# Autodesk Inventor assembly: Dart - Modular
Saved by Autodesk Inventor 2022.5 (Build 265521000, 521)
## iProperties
Created: 2025-01
Part Number: Dart - Modular
Document SubType Name: Assembly
Designer: AdminForWorker
Title: Dart - Modular v12
Author: AdminForWorker
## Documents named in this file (4)
- c:\worker\convert-fusion-r06-cosv3\tmp\job-1\21\temp\files\90c813e5-3d50-4192-b371-2f6eccf932a4\4eac9b11-f6fd-4ff3-90d4-f019b96032f5.iam
- c:\worker\convert-fusion-r06-cosv3\tmp\job-1\21\temp\files\90c813e5-3d50-4192-b371-2f6eccf932a4\Modular - Placebo - Bayonet Connector v4.ipt
- c:\worker\convert-fusion-r06-cosv3\tmp\job-1\21\temp\files\90c813e5-3d50-4192-b371-2f6eccf932a4\Dart Modular.ipt
- c:\worker\convert-fusion-r06-cosv3\tmp\job-1\21\temp\files\90c813e5-3d50-4192-b371-2f6eccf932a4\Modular - Placedo - Cord Set v4.ipt
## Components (3 placed, 3 different names)
1. Modular - Placebo - Bayonet Connector v4:1
2. Dart Modular:1
3. Modular - Placedo - Cord Set v4:1
